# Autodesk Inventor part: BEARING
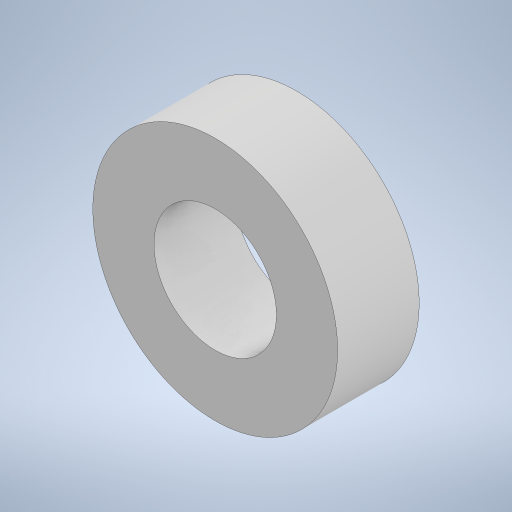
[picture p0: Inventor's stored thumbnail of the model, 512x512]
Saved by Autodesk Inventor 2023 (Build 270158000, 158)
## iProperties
Created: 2025-07
Part Number: BEARING
Material: Generic
Document SubType Name: Modeling
Designer: erjon
Density: 1 g/cm^3
Appearance: Default
Author: erjon
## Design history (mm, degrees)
feature "Base1"
body "Solid1"
